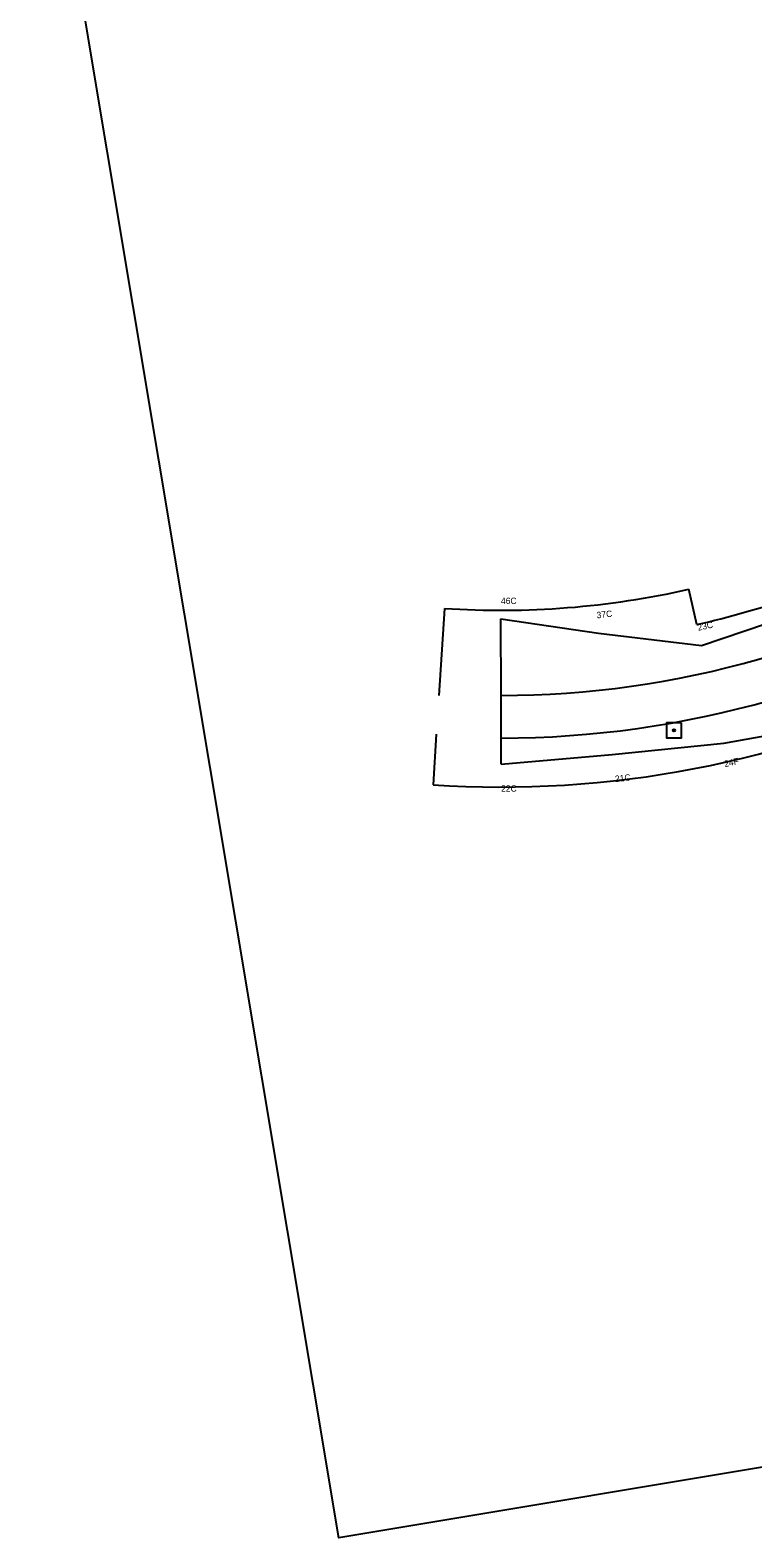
# Model space of a CAD drawing. Extents: x 1509010 to 1513406, y 898655 to 900162.
# Drawn here: x 1510177 to 1510516, y 899057 to 899765 of the extents above; entities that cross this region are included whole.
import ezdxf

# ---------------------------------------------------------------- set-up
doc = ezdxf.new("R2010")
doc.units = 0
for name, color, linetype in [('RD_HC_Survey', 7, 'Continuous'), ('RD_PD_CstnLmt', 7, 'Continuous'), ('RD_PD_CstnLmt_TX', 7, 'Continuous'), ('RD_PD_Final_TrvlWay', 7, 'Continuous'), ('RD_PD_RW', 7, 'Continuous'), ('RD_Sketch2', 7, 'Continuous')]:
    doc.layers.add(name, color=color, linetype=linetype)

msp = doc.modelspace()

# ---------------------------------------------------------------- linework, layer by layer
at = {"layer": 'RD_HC_Survey'}
msp.add_lwpolyline([(1510482.52, 899440.04), (1510475.45, 899440.04), (1510475.45, 899432.96), (1510482.52, 899432.96)], close=True, dxfattribs=at)
msp.add_circle((1510478.99, 899436.5), 0.5, dxfattribs=at)
at = {"layer": 'RD_PD_CstnLmt'}
for p, q in [((1510491.93, 899476.37), (1510536.79, 899491.54)), ((1510397.82, 899452.87), (1510397.8, 899488.82)), ((1510397.8, 899488.82), (1510443.64, 899482.1)), ((1510443.64, 899482.1), (1510491.93, 899476.37)), ((1510502.35, 899430.39), (1510554.72, 899439.85)), ((1510397.84, 899420.68), (1510397.84, 899432.87)), ((1510450.04, 899425.09), (1510502.35, 899430.39)), ((1510397.84, 899420.68), (1510450.04, 899425.09))]:
    msp.add_line(p, q, dxfattribs=at)
at = {"layer": 'RD_PD_Final_TrvlWay'}
msp.add_line((1510397.84, 899432.87), (1510397.82, 899452.87), dxfattribs=at)
for radius in [440, 460]:
    msp.add_arc((1510397.55, 899892.87), radius, 270.03596, 301.95202, dxfattribs=at)
at = {"layer": 'RD_PD_RW'}
for p, q in [((1510489.71, 899486.18), (1510485.95, 899502.76)), ((1510371.34, 899493.73), (1510368.65, 899452.84)), ((1510367.46, 899434.7), (1510365.9, 899410.91))]:
    msp.add_line(p, q, dxfattribs=at)
for radius, start, end in [(417, 282.76836, 295.50075), (400, 266.24308, 282.76836), (483, 266.24308, 295.50075)]:
    msp.add_arc((1510397.55, 899892.87), radius, start, end, dxfattribs=at)
at = {"layer": 'RD_Sketch2'}
msp.add_lwpolyline([(1510176.81, 899925.26), (1511597.17, 900162.3), (1511742.02, 899294.3), (1510321.67, 899057.27)], close=True, dxfattribs=at)

# ---------------------------------------------------------------- texts
at = {"layer": 'RD_PD_CstnLmt_TX'}
for s, rotation, p in [('46C', 0.03596, (1510397.8, 899495.82)), ('37C', 6.40216, (1510442.86, 899489.06)), ('23C', 12.76835, (1510490.39, 899483.19)), ('24F', 12.76835, (1510502.91, 899419.18)), ('21C', 6.40216, (1510451.48, 899412.17)), ('22C', 0.03596, (1510397.85, 899407.68))]:
    msp.add_text(s, height=3, rotation=rotation, dxfattribs=at).set_placement(p)

doc.saveas('drawing.dxf')
